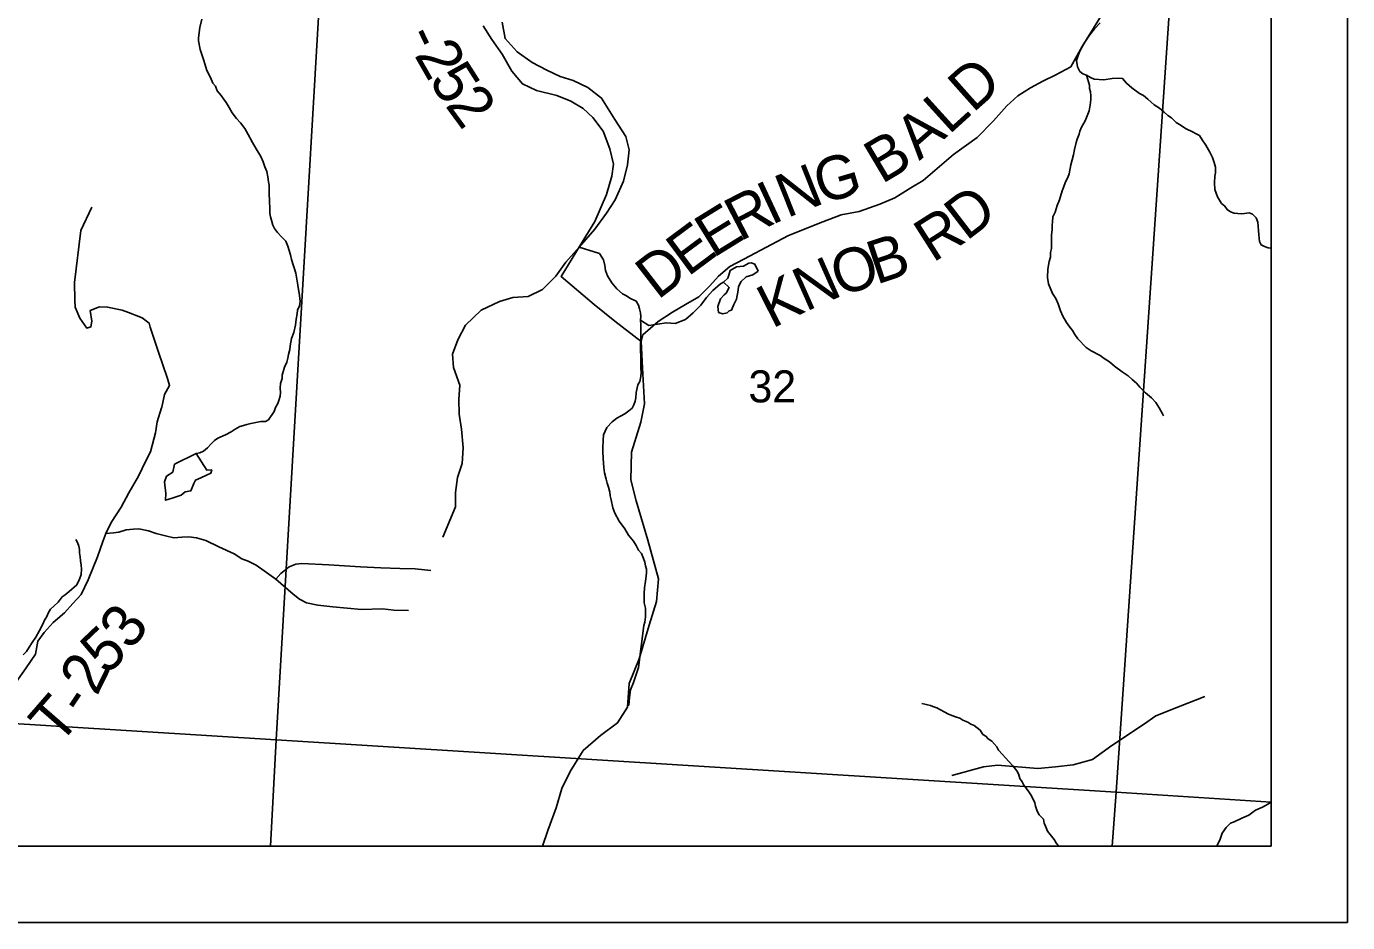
# Model space of a CAD drawing. Extents: x 0 to 34, y 0 to 22.
# Drawn here: x 7.274 to 9, y 14 to 15.171 of the extents above; entities that cross this region are included whole.
import ezdxf

# ---------------------------------------------------------------- set-up
doc = ezdxf.new("R2010")
doc.units = 0
for name, color, linetype in [('GM_X_Corporation', 7, 'Continuous'), ('GM_X_County_Road', 7, 'Continuous'), ('GM_X_County_Road_Text', 7, 'Continuous'), ('GM_X_Minor_Lake', 7, 'Continuous'), ('GM_X_Minor_River', 7, 'Continuous'), ('GM_X_Section_Text', 7, 'Continuous'), ('GM_X_Township_Road', 7, 'Continuous'), ('GM_X_Township_Road_Text', 7, 'Continuous'), ('SH_Data', 7, 'Continuous')]:
    doc.layers.add(name, color=color, linetype=linetype)

msp = doc.modelspace()

# ---------------------------------------------------------------- linework, layer by layer
at = {"layer": 'GM_X_Corporation'}
for points in [[(3.3441, 14.1), (8.9, 14.1), (8.9, 20.9), (2.1, 20.9), (2.1, 16.1353), (2.1457, 16.065), (2.3447, 15.6926), (2.4297, 15.5215), (2.465, 15.4504), (2.4884, 15.4033), (2.5769, 15.2135), (2.7849, 14.8403), (2.8931, 14.6544), (3.0297, 14.4867), (3.1386, 14.3654), (3.228, 14.2415)], [(5.4627, 14.1), (8.9, 14.1), (8.9, 16.2015), (7.873, 16.2628), (7.7162, 16.2721), (7.5782, 16.28), (6.6249, 16.3344), (6.6163, 16.2457), (5.9321, 16.289), (5.8351, 16.2952), (5.6497, 16.3069), (5.6022, 16.3258), (5.5809, 15.9822), (5.4893, 14.5091), (5.4833, 14.4122), (5.4763, 14.3006)], [(6.5568, 15.3381), (7.66, 15.265), (7.6002, 14.2387), (6.4864, 14.308), (6.5491, 15.2271)], [(7.66, 15.265), (8.7674, 15.1938), (8.6977, 14.1705), (7.6002, 14.2387)], [(8.9, 14.1574), (8.9, 15.1859), (8.7674, 15.1938), (8.6977, 14.1705)], [(6.4745, 14.1), (7.5926, 14.1), (7.6002, 14.2387), (6.4864, 14.308), (6.4814, 14.2281)], [(7.5926, 14.1), (8.6922, 14.1), (8.6977, 14.1705), (7.6002, 14.2387)], [(8.6922, 14.1), (8.9, 14.1), (8.9, 14.1574), (8.6977, 14.1705)]]:
    msp.add_lwpolyline(points, close=True, dxfattribs=at)
at = {"layer": 'GM_X_County_Road'}
msp.add_lwpolyline([(7.9479, 14.1), (7.9548, 14.1203), (7.9658, 14.1499), (7.9734, 14.1753), (7.9841, 14.1973), (8.0012, 14.2246), (8.0236, 14.2444), (8.0461, 14.2607), (8.059, 14.2812), (8.0613, 14.3123), (8.0742, 14.3446), (8.0872, 14.3883), (8.0971, 14.4194), (8.0998, 14.449), (8.0858, 14.4995), (8.0703, 14.5511), (8.0635, 14.5782), (8.0642, 14.6145), (8.0764, 14.6537), (8.0814, 14.6776), (8.0788, 14.7247), (8.0769, 14.7592), (8.0792, 14.7679), (8.0993, 14.785), (8.1179, 14.7975), (8.135, 14.8074), (8.1525, 14.8173), (8.1666, 14.8317), (8.178, 14.8446), (8.1928, 14.8571), (8.2111, 14.8666), (8.2472, 14.8856), (8.2696, 14.8974), (8.3144, 14.9152), (8.3383, 14.9243), (8.3619, 14.9288), (8.3889, 14.9383), (8.4086, 14.9467), (8.4291, 14.9596), (8.4455, 14.9695), (8.485, 15.0032), (8.5162, 15.0256), (8.5375, 15.0473), (8.5546, 15.067), (8.569, 15.0799), (8.5857, 15.0902), (8.6017, 15.0993), (8.6188, 15.1073), (8.6382, 15.1179), (8.653, 15.1445), (8.6793, 15.1866)], dxfattribs=at)
at = {"layer": 'GM_X_Minor_Lake'}
for points in [[(8.1846, 14.8364), (8.1918, 14.8296), (8.188, 14.822), (8.1854, 14.8198), (8.1808, 14.8148), (8.177, 14.8046), (8.1782, 14.797), (8.1835, 14.7952), (8.1895, 14.7967), (8.1918, 14.7989), (8.1948, 14.8001), (8.1982, 14.8073), (8.2013, 14.8145), (8.2035, 14.8262), (8.2043, 14.8311), (8.2077, 14.8376), (8.2141, 14.8436), (8.2228, 14.8463), (8.23, 14.8508)], [(8.23, 14.8508), (8.2255, 14.8599), (8.2206, 14.8618), (8.2175, 14.8614), (8.2107, 14.8573), (8.2017, 14.8565), (8.1933, 14.852), (8.1914, 14.8455), (8.1903, 14.8417), (8.1846, 14.8364)], [(7.4956, 14.6126), (7.4673, 14.5986), (7.4651, 14.5884), (7.4567, 14.5831), (7.4541, 14.5759), (7.456, 14.5607), (7.4556, 14.5516), (7.4639, 14.5543)], [(7.4639, 14.5543), (7.476, 14.5581), (7.481, 14.5626), (7.4885, 14.5641), (7.4923, 14.5736), (7.4946, 14.5781), (7.5014, 14.5808), (7.509, 14.5846), (7.5146, 14.5869), (7.5158, 14.5914), (7.5093, 14.591), (7.4956, 14.6126)]]:
    msp.add_lwpolyline(points, dxfattribs=at)
at = {"layer": 'GM_X_Minor_River'}
for points in [[(7.5028, 15.1801), (7.5004, 15.1692), (7.4986, 15.1559), (7.4985, 15.1517), (7.5006, 15.1403), (7.5057, 15.1262), (7.5096, 15.1132), (7.514, 15.104), (7.5173, 15.0967), (7.5206, 15.0925), (7.5231, 15.0864), (7.528, 15.0802), (7.5313, 15.076), (7.5346, 15.0714), (7.5387, 15.0648), (7.5427, 15.0579), (7.5483, 15.0503), (7.5535, 15.0445), (7.559, 15.0372), (7.5634, 15.0295), (7.5689, 15.0191), (7.5737, 15.0107), (7.58, 15.0007), (7.5832, 14.9938), (7.585, 14.9874), (7.5876, 14.9809), (7.589, 14.974), (7.59, 14.9675), (7.5907, 14.9633), (7.5909, 14.9576), (7.5909, 14.9523), (7.5914, 14.9424), (7.5916, 14.9326), (7.5919, 14.9269), (7.5926, 14.9219), (7.5944, 14.9158), (7.5958, 14.9108), (7.598, 14.9066), (7.6017, 14.9016), (7.6073, 14.8955), (7.6125, 14.8901), (7.6154, 14.8836), (7.6186, 14.8721), (7.62, 14.866), (7.6258, 14.8481), (7.6264, 14.8431), (7.6285, 14.8328), (7.6305, 14.8191), (7.6312, 14.8115), (7.6303, 14.8055), (7.6279, 14.7998), (7.6275, 14.7952), (7.6262, 14.7881), (7.6253, 14.7805), (7.6233, 14.771), (7.6201, 14.7631), (7.6184, 14.7532), (7.6179, 14.7487), (7.6163, 14.7419), (7.6151, 14.7374), (7.6139, 14.7321), (7.6111, 14.7257), (7.6079, 14.7151), (7.6078, 14.7105), (7.6058, 14.7041), (7.6053, 14.698), (7.6056, 14.6923), (7.6051, 14.6878), (7.6039, 14.6832), (7.6023, 14.678), (7.5992, 14.6727), (7.5972, 14.6674), (7.5902, 14.6569), (7.586, 14.6547), (7.5799, 14.6544)], [(7.8176, 14.5036), (7.8344, 14.543), (7.8345, 14.5619), (7.8368, 14.5816), (7.8429, 14.5998), (7.8445, 14.6203), (7.8423, 14.6446), (7.8393, 14.6643), (7.8386, 14.6833), (7.8402, 14.7022), (7.8319, 14.725), (7.8305, 14.7424), (7.8374, 14.7614), (7.8473, 14.7803), (7.8678, 14.8), (7.892, 14.8113), (7.9094, 14.8165), (7.9291, 14.818), (7.9481, 14.827), (7.9655, 14.8444), (7.9785, 14.8626), (7.9959, 14.8822), (8.0165, 14.9057), (8.0317, 14.9269), (8.0431, 14.9443), (8.0537, 14.9685), (8.0591, 14.9897), (8.0614, 15.0095), (8.057, 15.0269), (8.0426, 15.0489), (8.0253, 15.0771), (8.0072, 15.0908), (7.9883, 15.0999), (7.9709, 15.1053), (7.9535, 15.1137), (7.9346, 15.1236), (7.915, 15.1373), (7.8992, 15.1548), (7.8954, 15.176)], [(8.6766, 15.1752), (8.6692, 15.1673), (8.6626, 15.1591), (8.6568, 15.1501), (8.6521, 15.1418), (8.6494, 15.1361), (8.6474, 15.1312), (8.6458, 15.1263), (8.6471, 15.1179), (8.6501, 15.1118), (8.6542, 15.1087), (8.6587, 15.1071), (8.6639, 15.104), (8.6688, 15.1016), (8.6817, 15.1007), (8.6923, 15.1024), (8.701, 15.103), (8.706, 15.1025), (8.7112, 15.0967), (8.7179, 15.0902), (8.728, 15.0832), (8.7332, 15.0804), (8.7388, 15.0758), (8.7474, 15.0684), (8.7541, 15.0637), (8.7597, 15.0591), (8.7653, 15.0541), (8.7698, 15.051), (8.7762, 15.0452), (8.7803, 15.0424), (8.7889, 15.037), (8.7972, 15.033), (8.802, 15.0303), (8.8065, 15.0283), (8.8099, 15.0226), (8.8146, 15.0153), (8.8202, 15.0064), (8.8235, 14.9996), (8.8256, 14.9927), (8.8274, 14.9866), (8.8273, 14.9794), (8.8264, 14.9748), (8.8259, 14.9661), (8.8265, 14.9577), (8.8301, 14.9482), (8.8353, 14.9394), (8.8398, 14.9359), (8.8427, 14.9313), (8.8468, 14.9285), (8.8517, 14.9265), (8.8612, 14.926), (8.8654, 14.9263), (8.8714, 14.927), (8.8756, 14.9254), (8.8804, 14.9204), (8.8826, 14.915), (8.8842, 14.8983), (8.8848, 14.8895), (8.887, 14.8853), (8.8915, 14.883), (8.8964, 14.8814), (8.9, 14.881)], [(8.6587, 15.1071), (8.6626, 15.0941), (8.6629, 15.0896), (8.664, 15.085), (8.6647, 15.0801), (8.6646, 15.0759), (8.6641, 15.0709), (8.6624, 15.0603), (8.6573, 15.0471), (8.6522, 15.0392), (8.6502, 15.034), (8.6494, 15.0298), (8.6466, 15.0234), (8.6454, 15.0192), (8.6433, 15.0098), (8.6417, 15.003), (8.6401, 14.9965), (8.6384, 14.9897), (8.6363, 14.978), (8.6344, 14.9731), (8.6316, 14.9674), (8.6288, 14.9603), (8.6269, 14.9557), (8.6236, 14.944), (8.6205, 14.9369), (8.6177, 14.9278), (8.6149, 14.9218), (8.6144, 14.9153), (8.6139, 14.9108), (8.6138, 14.9047), (8.6133, 14.8982), (8.613, 14.8804), (8.6118, 14.8751), (8.6117, 14.8694), (8.6101, 14.8634), (8.6084, 14.8535), (8.6078, 14.8425), (8.6092, 14.8345), (8.6143, 14.8219), (8.6187, 14.815), (8.622, 14.8081), (8.6249, 14.7989), (8.6278, 14.7921), (8.6329, 14.784), (8.637, 14.7778), (8.6407, 14.7732), (8.6436, 14.7682), (8.6477, 14.7625), (8.6585, 14.7513), (8.6648, 14.747), (8.6769, 14.7407), (8.6821, 14.7368), (8.6888, 14.7326), (8.6955, 14.7267), (8.7053, 14.7194), (8.7131, 14.7143), (8.7187, 14.7096), (8.7243, 14.7046), (8.7284, 14.6996), (8.7358, 14.6919), (8.7437, 14.6853), (8.7493, 14.6795), (8.7537, 14.6726), (8.7577, 14.6653), (8.7595, 14.662)], [(7.9959, 14.8822), (8.0224, 14.874), (8.0279, 14.8656), (8.0293, 14.8583), (8.0303, 14.8518), (8.0329, 14.845), (8.0388, 14.8358), (8.0451, 14.8277), (8.0525, 14.8215), (8.0578, 14.8187), (8.0623, 14.8156), (8.0705, 14.8117), (8.0735, 14.8067), (8.0749, 14.8017), (8.076, 14.7964), (8.0763, 14.7918), (8.0762, 14.7869), (8.0764, 14.7808), (8.0763, 14.7747), (8.0766, 14.7687), (8.0762, 14.7474), (8.0765, 14.7398), (8.0763, 14.7314), (8.0766, 14.7235), (8.0769, 14.7189), (8.0764, 14.7132), (8.0751, 14.7068), (8.0728, 14.7023), (8.0703, 14.6924), (8.0698, 14.6856), (8.069, 14.6811), (8.0674, 14.6765), (8.0651, 14.672), (8.0608, 14.6683), (8.0555, 14.6646), (8.0501, 14.6616), (8.0451, 14.6591), (8.039, 14.6542), (8.032, 14.6468), (8.0277, 14.637), (8.0272, 14.6297), (8.027, 14.6203), (8.0269, 14.6153), (8.0275, 14.6062), (8.0281, 14.5944), (8.0291, 14.5876), (8.0312, 14.5792), (8.0323, 14.5738), (8.0341, 14.5689), (8.0359, 14.5624), (8.0365, 14.5574), (8.0376, 14.5521), (8.04, 14.5418), (8.0426, 14.5349), (8.0484, 14.5242), (8.0555, 14.5142), (8.0606, 14.5061), (8.0669, 14.4981), (8.0702, 14.4927), (8.0735, 14.4866), (8.0772, 14.4819), (8.0798, 14.4754), (8.0816, 14.4709), (8.0826, 14.4659), (8.0837, 14.4617), (8.084, 14.4575), (8.0835, 14.4526), (8.0827, 14.4458), (8.0814, 14.4371), (8.0809, 14.4299), (8.0808, 14.4242), (8.081, 14.4177), (8.0824, 14.4108), (8.0827, 14.4063), (8.0826, 14.3994), (8.0817, 14.3926), (8.0805, 14.3881)], [(8.0762, 14.7868), (8.087, 14.78), (8.0983, 14.7815), (8.11, 14.7834), (8.1214, 14.7827), (8.135, 14.788), (8.1449, 14.7963), (8.1547, 14.8065), (8.1623, 14.8164), (8.1706, 14.8258), (8.1804, 14.8345), (8.1846, 14.8364)], [(7.5799, 14.6544), (7.567, 14.652), (7.5617, 14.6505), (7.5571, 14.6491), (7.5525, 14.648), (7.5464, 14.6447), (7.5414, 14.641), (7.5338, 14.637), (7.5239, 14.6326), (7.5196, 14.6296), (7.515, 14.6255), (7.5104, 14.6203), (7.505, 14.6158), (7.5004, 14.6136), (7.4956, 14.6126)], [(7.2693, 14.3498), (7.2739, 14.3543), (7.2774, 14.3599), (7.2813, 14.366), (7.286, 14.3727), (7.2907, 14.3817), (7.295, 14.3896), (7.2973, 14.3949), (7.3001, 14.3991), (7.3024, 14.4051), (7.3052, 14.4092), (7.3094, 14.4133), (7.3152, 14.4185), (7.3202, 14.4253), (7.3244, 14.4283), (7.3294, 14.4323), (7.3394, 14.4413), (7.343, 14.4484), (7.3453, 14.4545), (7.3455, 14.4617), (7.3452, 14.467), (7.3442, 14.4727), (7.3439, 14.4777), (7.3432, 14.483), (7.3429, 14.4872), (7.3422, 14.4917), (7.3404, 14.4963), (7.3382, 14.5005)], [(8.0805, 14.3881), (8.0736, 14.3334), (8.0705, 14.3239), (8.0671, 14.3137), (8.063, 14.3039), (8.0618, 14.294), (8.0607, 14.2838), (8.0603, 14.2842)], [(8.6228, 14.1), (8.6198, 14.1033), (8.6168, 14.1083), (8.6113, 14.1149), (8.608, 14.1195), (8.6054, 14.126), (8.6036, 14.1298), (8.6025, 14.1351), (8.597, 14.1409), (8.5944, 14.1455), (8.5922, 14.152), (8.5912, 14.1566), (8.5868, 14.1654), (8.5827, 14.1723), (8.5794, 14.1762), (8.5768, 14.1796), (8.5746, 14.1838), (8.5717, 14.1884), (8.5699, 14.1945), (8.5677, 14.1984), (8.5625, 14.2049), (8.5573, 14.2103), (8.5528, 14.2153), (8.5491, 14.2196), (8.5439, 14.2254), (8.5417, 14.2296), (8.535, 14.2369), (8.5302, 14.24), (8.5272, 14.2435), (8.5234, 14.2458), (8.5201, 14.2512), (8.5119, 14.2574), (8.5078, 14.259), (8.5036, 14.2617), (8.4973, 14.2645), (8.4935, 14.2668), (8.4875, 14.2688), (8.4841, 14.27), (8.4785, 14.2724), (8.4728, 14.2752), (8.4631, 14.2803), (8.4582, 14.2822), (8.4548, 14.2834), (8.451, 14.2846), (8.4476, 14.2855), (8.4439, 14.2863)], [(8.8285, 14.1), (8.8296, 14.101), (8.8331, 14.1078), (8.8363, 14.1168), (8.8414, 14.1243), (8.8471, 14.1299), (8.8517, 14.1317), (8.862, 14.1365), (8.8708, 14.1405), (8.8796, 14.1468), (8.8888, 14.1509), (8.8965, 14.1553), (8.9, 14.1576)]]:
    msp.add_lwpolyline(points, dxfattribs=at)
at = {"layer": 'GM_X_Township_Road'}
for points in [[(7.8706, 15.1712), (7.882, 15.1534), (7.8953, 15.1344), (7.9078, 15.112), (7.9218, 15.0957), (7.9401, 15.0869), (7.9666, 15.0805), (7.9852, 15.0732), (8.0012, 15.0634), (8.0137, 15.0516), (8.0274, 15.0337), (8.0361, 15.0106), (8.0406, 14.9908), (8.0387, 14.9749), (8.0315, 14.951), (8.0163, 14.916), (7.9965, 14.883), (7.9725, 14.8439), (8.0154, 14.8074), (8.0427, 14.7858), (8.0769, 14.7592)], [(7.3371, 14.8129), (7.3363, 14.8359), (7.3449, 14.9041), (7.359, 14.9347)], [(7.4505, 14.6734), (7.4541, 14.6897), (7.4608, 14.7017), (7.4578, 14.7106), (7.4464, 14.745), (7.4355, 14.7776), (7.4339, 14.7831), (7.425, 14.7901), (7.4072, 14.7968), (7.3987, 14.8001), (7.3797, 14.804), (7.3692, 14.8044), (7.3568, 14.7994), (7.3591, 14.7858), (7.3579, 14.7781), (7.3525, 14.7766), (7.3436, 14.7897), (7.3374, 14.804), (7.3371, 14.8129)], [(7.2447, 14.298), (7.2598, 14.3134), (7.2735, 14.3329), (7.2854, 14.3504), (7.2885, 14.3675), (7.2967, 14.3791), (7.3084, 14.3921), (7.3234, 14.4048), (7.3344, 14.4167), (7.3453, 14.4287), (7.3545, 14.4479), (7.3665, 14.4776), (7.3734, 14.4978), (7.3775, 14.5081), (7.3846, 14.5228), (7.3976, 14.5426), (7.4076, 14.5614), (7.4202, 14.5833), (7.4298, 14.6032), (7.4356, 14.6151), (7.4425, 14.6398), (7.4445, 14.6541), (7.4503, 14.6726), (7.4505, 14.6734)], [(7.3775, 14.5081), (7.3875, 14.5092), (7.3944, 14.51), (7.4039, 14.513), (7.4135, 14.5138), (7.4204, 14.5142), (7.433, 14.5119), (7.4433, 14.5081), (7.4555, 14.505), (7.4663, 14.5027), (7.4766, 14.5035), (7.4858, 14.5039), (7.4957, 14.5027), (7.5083, 14.4989), (7.5251, 14.4909), (7.545, 14.4817), (7.555, 14.4752), (7.5634, 14.4721), (7.5737, 14.4668), (7.5844, 14.4595), (7.5997, 14.4488), (7.6223, 14.4289), (7.6303, 14.4224), (7.6395, 14.4178), (7.6544, 14.4148), (7.6739, 14.4125), (7.7117, 14.409), (7.7389, 14.4098), (7.7538, 14.4083), (7.7729, 14.4075)], [(7.5997, 14.4488), (7.6062, 14.4561), (7.6169, 14.4645), (7.6257, 14.4683), (7.6337, 14.4691), (7.6689, 14.4672), (7.6895, 14.466), (7.7102, 14.4645), (7.7366, 14.4633), (7.7614, 14.4626), (7.7818, 14.4621), (7.8021, 14.4597)], [(8.4827, 14.192), (8.5241, 14.2035), (8.5425, 14.2058), (8.5953, 14.2013), (8.6183, 14.2036), (8.6413, 14.2059), (8.6665, 14.2128), (8.6918, 14.2311), (8.7332, 14.2587), (8.7493, 14.2702), (8.7791, 14.2817), (8.8136, 14.2955)]]:
    msp.add_lwpolyline(points, dxfattribs=at)
at = {"layer": 'SH_Data'}
for p, q in [((9, 21), (9, 14)), ((8.9, 20.9), (8.9, 14.1)), ((2.1, 14.1), (8.9, 14.1)), ((2, 14), (9, 14))]:
    msp.add_line(p, q, dxfattribs=at)

# ---------------------------------------------------------------- texts
at = {"layer": 'GM_X_County_Road_Text'}
for s, rotation, p in [('D', 41.6921, (8.5103, 15.0567)), ('L', 42.207, (8.4789, 15.0282)), ('A', 41.1698, (8.4404, 14.9946)), ('B', 30.7437, (8.3912, 14.9641)), ('G', 16.3587, (8.3124, 14.938)), ('N', 21.68, (8.2673, 14.92)), ('I', 25.0307, (8.2469, 14.9105)), ('R', 27.388, (8.206, 14.8893)), ('D', 37.5563, (8.5019, 14.8895)), ('E', 31.6756, (8.1709, 14.8675)), ('E', 36.6102, (8.1378, 14.8429)), ('R', 32.4507, (8.458, 14.8613)), ('B', 18.555, (8.3842, 14.833)), ('O', 18.0223, (8.3361, 14.8173)), ('D', 37.7048, (8.0985, 14.8125)), ('N', 23.9095, (8.2918, 14.7976)), ('K', 26.9397, (8.248, 14.7753))]:
    msp.add_text(s, height=0.0568, rotation=rotation, dxfattribs=at).set_placement(p)
at = {"layer": 'GM_X_Section_Text'}
msp.add_text('32', height=0.04186, rotation=0, dxfattribs=at).set_placement((8.2172, 14.6795))
at = {"layer": 'GM_X_Township_Road_Text'}
for s, rotation, p in [('-', 295.475, (7.7676, 15.1585)), ('2', 299.7826, (7.7798, 15.1333)), ('5', 302.523, (7.7988, 15.1004)), ('2', 306.3992, (7.8199, 15.0674)), ('3', 53.6389, (7.4105, 14.3542)), ('5', 43.5868, (7.378, 14.322)), ('2', 63.8715, (7.3657, 14.2948)), ('T', 49.0003, (7.3159, 14.23)), ('-', 56.0378, (7.3484, 14.2681))]:
    msp.add_text(s, height=0.0568, rotation=rotation, dxfattribs=at).set_placement(p)

doc.saveas('drawing.dxf')
